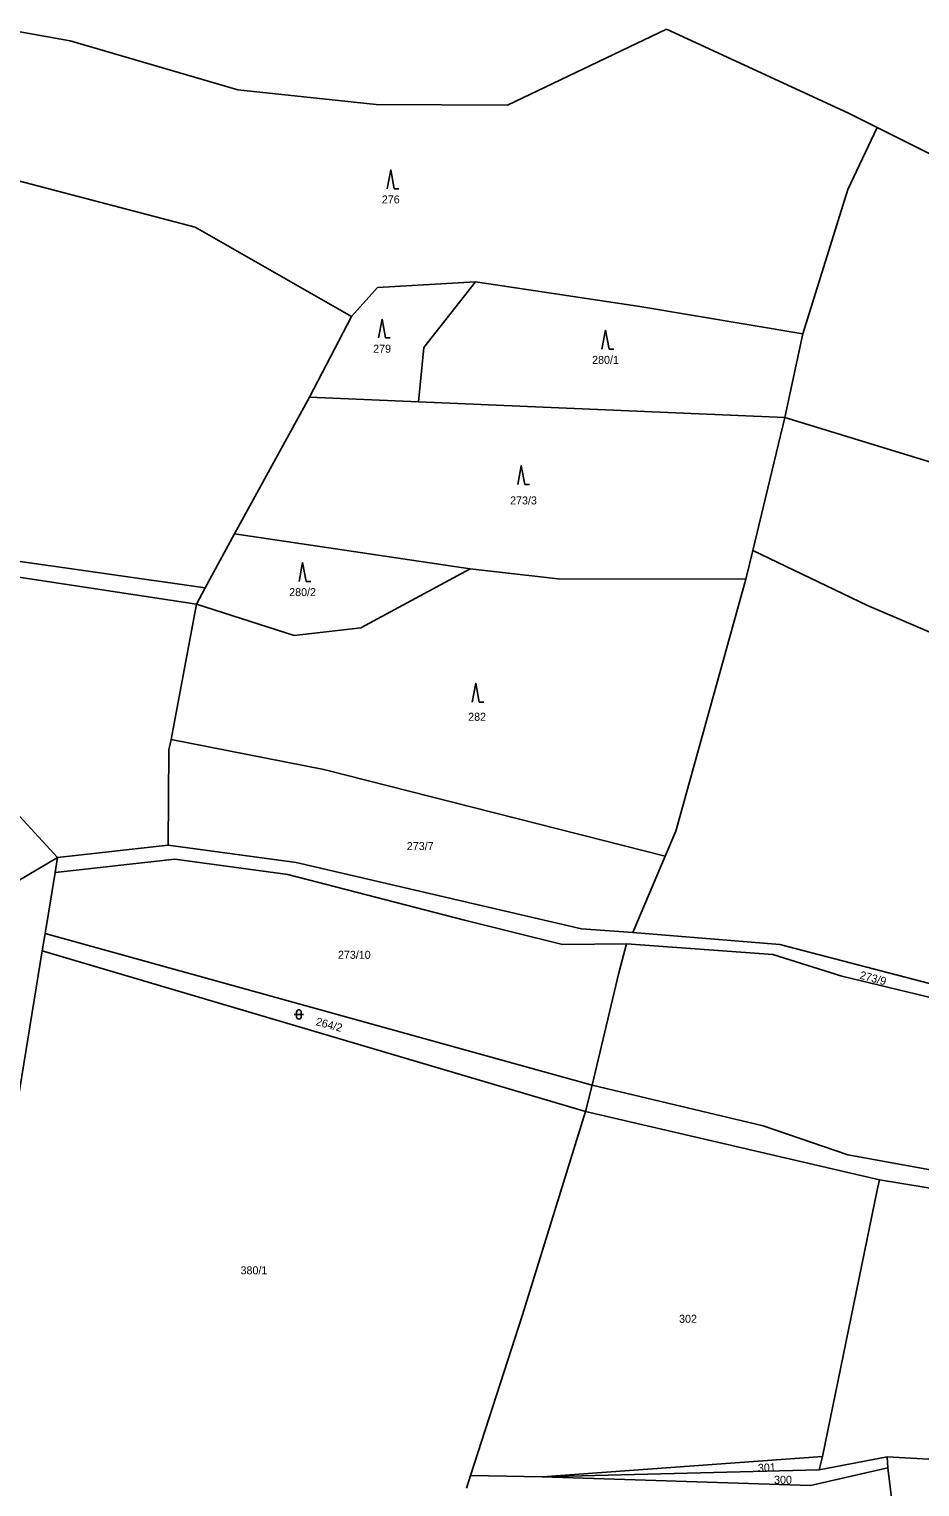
# Model space of a CAD drawing. Extents: x -791548 to -789311, y -1142631 to -1140855.
# Drawn here: x -791288.6 to -791099.4, y -1141698.3 to -1141388.6 of the extents above; entities that cross this region are included whole.
import ezdxf
from ezdxf.enums import TextEntityAlignment as Align

# ---------------------------------------------------------------- set-up
doc = ezdxf.new("R2010")
doc.units = 0
doc.header["$LTSCALE"] = 0.68
doc.layers.add('1', color=7, linetype='Continuous', lineweight=25)
doc.layers.add('3', color=7, linetype='Continuous', lineweight=25)
doc.layers.add('2', color=7, linetype='Continuous')

msp = doc.modelspace()

# ---------------------------------------------------------------- linework, layer by layer
at = {"layer": '1'}
for p, q in [((-791279.89, -1141391.04), (-791291.36, -1141389.04)), ((-791153.2, -1141388.58), (-791186.96, -1141404.71)), ((-791114.71, -1141406.37), (-791153.2, -1141388.58)), ((-791244.28, -1141401.44), (-791279.89, -1141391.04)), ((-791214.86, -1141404.6), (-791244.28, -1141401.44)), ((-791186.96, -1141404.71), (-791214.86, -1141404.6)), ((-791114.71, -1141406.37), (-791108.44, -1141409.5)), ((-791114.72, -1141422.66), (-791108.44, -1141409.5)), ((-791108.44, -1141409.5), (-791057.55, -1141434.87)), ((-791253.36, -1141430.65), (-791316.37, -1141414.15)), ((-791124.23, -1141453.34), (-791114.72, -1141422.66)), ((-791220.12, -1141449.64), (-791253.36, -1141430.65)), ((-791214.56, -1141443.44), (-791220.12, -1141449.64)), ((-791193.79, -1141442.27), (-791214.56, -1141443.44)), ((-791204.76, -1141456.19), (-791193.79, -1141442.27)), ((-791158.84, -1141447.48), (-791193.79, -1141442.27)), ((-791124.23, -1141453.34), (-791158.84, -1141447.48)), ((-791128.04, -1141471.09), (-791124.23, -1141453.34)), ((-791205.91, -1141467.74), (-791204.76, -1141456.19)), ((-791205.91, -1141467.74), (-791229.05, -1141466.78)), ((-791128.04, -1141471.09), (-791205.91, -1141467.74)), ((-791134.86, -1141499.36), (-791128.04, -1141471.09)), ((-791079.72, -1141485.89), (-791128.04, -1141471.09)), ((-791251.2, -1141507.28), (-791244.98, -1141495.84)), ((-791244.98, -1141495.84), (-791194.94, -1141503.21)), ((-791304.05, -1141499.75), (-791251.2, -1141507.28)), ((-791136.33, -1141505.46), (-791134.86, -1141499.36)), ((-791110.48, -1141511.03), (-791134.86, -1141499.36)), ((-791253.04, -1141510.74), (-791303.73, -1141503.05)), ((-791218.1, -1141515.77), (-791194.94, -1141503.21)), ((-791194.94, -1141503.21), (-791176.21, -1141505.37)), ((-791251.2, -1141507.28), (-791253.04, -1141510.74)), ((-791176.21, -1141505.37), (-791136.33, -1141505.46)), ((-791151.22, -1141558.95), (-791136.33, -1141505.46)), ((-791253.04, -1141510.74), (-791258.43, -1141539.49)), ((-791253.04, -1141510.74), (-791232.33, -1141517.38)), ((-791084.34, -1141522.3), (-791110.48, -1141511.03)), ((-791232.33, -1141517.38), (-791218.1, -1141515.77)), ((-791258.93, -1141541.68), (-791258.43, -1141539.49)), ((-791258.43, -1141539.49), (-791225.98, -1141545.87)), ((-791259.04, -1141561.99), (-791258.93, -1141541.68)), ((-791300.37, -1141545.28), (-791282.55, -1141564.55)), ((-791225.98, -1141545.87), (-791153.47, -1141564.31)), ((-791153.47, -1141564.31), (-791151.22, -1141558.95)), ((-791282.55, -1141564.55), (-791259.04, -1141561.99)), ((-791259.04, -1141561.99), (-791231.86, -1141565.62)), ((-791329.63, -1141592.51), (-791282.55, -1141564.55)), ((-791282.55, -1141564.55), (-791283.08, -1141567.79)), ((-791257.64, -1141564.95), (-791283.08, -1141567.79)), ((-791233.62, -1141568.22), (-791257.64, -1141564.95)), ((-791231.86, -1141565.62), (-791171.29, -1141579.76)), ((-791160.39, -1141580.52), (-791153.47, -1141564.31)), ((-791283.08, -1141567.79), (-791285.21, -1141580.72)), ((-791196.11, -1141577.9), (-791233.62, -1141568.22)), ((-791175.27, -1141583.06), (-791196.11, -1141577.9)), ((-791285.21, -1141580.72), (-791285.82, -1141584.43)), ((-791285.21, -1141580.72), (-791168.97, -1141612.96)), ((-791171.29, -1141579.76), (-791160.39, -1141580.52)), ((-791129.12, -1141583.07), (-791160.39, -1141580.52)), ((-791285.82, -1141584.43), (-791292.76, -1141627.2)), ((-791170.42, -1141618.57), (-791285.82, -1141584.43)), ((-791161.7, -1141582.94), (-791175.27, -1141583.06)), ((-791163.35, -1141589.1), (-791161.7, -1141582.94)), ((-791130.65, -1141585.19), (-791161.7, -1141582.94)), ((-791085.44, -1141594.43), (-791129.12, -1141583.07)), ((-791115.96, -1141589.76), (-791130.65, -1141585.19)), ((-791168.97, -1141612.96), (-791163.35, -1141589.1)), ((-791087.93, -1141596.55), (-791115.96, -1141589.76)), ((-791170.42, -1141618.57), (-791168.97, -1141612.96)), ((-791168.97, -1141612.96), (-791132.7, -1141621.56)), ((-791183.8, -1141661.73), (-791170.42, -1141618.57)), ((-791107.99, -1141633.07), (-791170.42, -1141618.57)), ((-791132.7, -1141621.56), (-791114.69, -1141627.72)), ((-791114.69, -1141627.72), (-791074.08, -1141635.2)), ((-791108.35, -1141634.92), (-791107.99, -1141633.07)), ((-791077.08, -1141638.15), (-791107.99, -1141633.07)), ((-791120.06, -1141691.82), (-791108.35, -1141634.92)), ((-791194.85, -1141695.89), (-791183.8, -1141661.73)), ((-791179.61, -1141696.2), (-791120.06, -1141691.82)), ((-791120.06, -1141691.82), (-791120.74, -1141694.69)), ((-791106.31, -1141691.9), (-791120.74, -1141694.69)), ((-791106.31, -1141691.9), (-791073.79, -1141693.75)), ((-791106.16, -1141694.27), (-791106.31, -1141691.9)), ((-791195.71, -1141698.56), (-791194.85, -1141695.89)), ((-791194.85, -1141695.89), (-791179.61, -1141696.2)), ((-791120.74, -1141694.69), (-791179.61, -1141696.2)), ((-791179.61, -1141696.2), (-791122.62, -1141698.03)), ((-791122.62, -1141698.03), (-791106.16, -1141694.27)), ((-791099.53, -1141749.19), (-791106.16, -1141694.27))]:
    msp.add_line(p, q, dxfattribs=at)
msp.add_lwpolyline([(-791244.98, -1141495.84), (-791229.05, -1141466.78), (-791220.12, -1141449.64)], dxfattribs=at)
at = {"layer": '3'}
for p, q in [((-791211.03, -1141422.48), (-791210.034, -1141422.48)), ((-791212.87, -1141454.2), (-791211.874, -1141454.2)), ((-791165.41, -1141456.57), (-791164.414, -1141456.57)), ((-791183.31, -1141485.33), (-791182.314, -1141485.33)), ((-791229.76, -1141505.91), (-791228.764, -1141505.91)), ((-791192.98, -1141531.57), (-791191.984, -1141531.57)), ((-791232.291, -1141597.931), (-791230.289, -1141597.931)), ((-791231.791, -1141597.431), (-791231.791, -1141598.432)), ((-791230.789, -1141598.432), (-791230.789, -1141597.431))]:
    msp.add_line(p, q, dxfattribs=at)
for points in [[(-791211.03, -1141422.48), (-791211.78, -1141418.48), (-791212.53, -1141422.48)], [(-791212.87, -1141454.2), (-791213.62, -1141450.2), (-791214.37, -1141454.2)], [(-791165.41, -1141456.57), (-791166.16, -1141452.57), (-791166.91, -1141456.57)], [(-791183.31, -1141485.33), (-791184.06, -1141481.33), (-791184.81, -1141485.33)], [(-791229.76, -1141505.91), (-791230.51, -1141501.91), (-791231.26, -1141505.91)], [(-791192.98, -1141531.57), (-791193.73, -1141527.57), (-791194.48, -1141531.57)]]:
    msp.add_lwpolyline(points, dxfattribs=at)
for centre, start, end in [((-791231.29, -1141597.4309), 0, 180), ((-791231.29, -1141598.4309), 180, 359.98789)]:
    msp.add_arc(centre, 0.5, start, end, dxfattribs=at)

# ---------------------------------------------------------------- texts
at = {"layer": '2'}
for s, p in [('276', (-791211.779, -1141425.612)), ('279', (-791213.619, -1141457.332)), ('280/1', (-791166.16, -1141459.702)), ('273/3', (-791183.58, -1141489.562)), ('280/2', (-791230.51, -1141509.042)), ('282', (-791193.439, -1141535.532)), ('273/7', (-791205.52, -1141563.002)), ('273/10', (-791219.52, -1141586.102)), ('380/1', (-791240.84, -1141653.142)), ('302', (-791148.639, -1141663.442)), ('300', (-791128.459, -1141697.642))]:
    msp.add_text(s, height=1.7, dxfattribs=at).set_placement(p, align=Align.CENTER)
for s, rotation, p in [('273/9', 345, (-791109.54, -1141591.0389)), ('264/2', 345, (-791225.07, -1141600.9089)), ('301', 3, (-791131.8505, -1141695.0389))]:
    msp.add_text(s, height=1.7, rotation=rotation, dxfattribs=at).set_placement(p, align=Align.CENTER)

doc.saveas('drawing.dxf')
